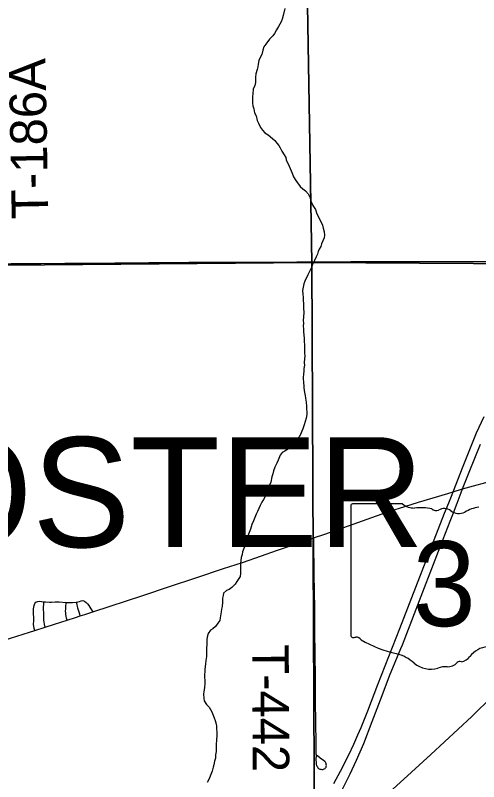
# Model space of a CAD drawing. Extents: x 0 to 34, y 0 to 22.
# Drawn here: x 6.446 to 7.165, y 18.473 to 19.661 of the extents above; entities that cross this region are included whole.
import ezdxf

# ---------------------------------------------------------------- set-up
doc = ezdxf.new("R2010")
doc.units = 0
for name, color, linetype in [('GM_X_County_Road', 7, 'Continuous'), ('GM_X_Minor_River', 7, 'Continuous'), ('GM_X_Section', 7, 'Continuous'), ('GM_X_State_Location', 7, 'Continuous'), ('GM_X_State_Route', 7, 'Continuous'), ('GM_X_State_Shield', 7, 'Continuous'), ('GM_X_Township_Road', 7, 'Continuous'), ('GM_X_Township_Road_Text', 7, 'Continuous'), ('GM_X_Township_Text', 7, 'Continuous')]:
    doc.layers.add(name, color=color, linetype=linetype)

msp = doc.modelspace()

# ---------------------------------------------------------------- linework, layer by layer
at = {"layer": 'GM_X_County_Road'}
msp.add_line((7.1398, 18.9272), (7.1984, 18.9434), dxfattribs=at)
for points in [[(6.3991, 19.2759), (6.4085, 19.2759), (6.4209, 19.2762), (6.4395, 19.2765), (6.4457, 19.2766), (6.4673, 19.2767), (6.4856, 19.2766), (6.5227, 19.277), (6.5724, 19.2772), (6.6003, 19.2775), (6.6345, 19.2778), (6.6532, 19.278), (6.6625, 19.278), (6.6904, 19.2783), (6.7153, 19.2786), (6.7463, 19.2787), (6.7711, 19.2787), (6.8478, 19.279)], [(6.8478, 19.279), (6.8518, 19.279), (6.8828, 19.2792), (6.8983, 19.2794), (6.9108, 19.2794), (6.9263, 19.2795), (6.9666, 19.2796), (6.9976, 19.2799), (7.0287, 19.2797), (7.0336, 19.2797)], [(7.0336, 19.2797), (7.0473, 19.2797), (7.072, 19.2796), (7.1029, 19.2797), (7.1215, 19.2797), (7.137, 19.2796), (7.1555, 19.2798), (7.1802, 19.28)], [(6.9143, 18.3538), (6.9217, 18.3612), (7.0032, 18.4357), (7.0604, 18.4882), (7.0903, 18.5154), (7.1541, 18.5743), (7.1635, 18.5838), (7.1761, 18.5962), (7.192, 18.6134), (7.2032, 18.626), (7.2991, 18.7318), (7.3555, 18.794), (7.3689, 18.8087)]]:
    msp.add_lwpolyline(points, dxfattribs=at)
at = {"layer": 'GM_X_Minor_River'}
for points in [[(6.8639, 19.672), (6.8614, 19.6614), (6.8596, 19.6557), (6.8581, 19.6515), (6.8544, 19.6442), (6.851, 19.6388), (6.848, 19.6335), (6.8451, 19.6296), (6.8402, 19.6246), (6.8346, 19.617), (6.8316, 19.6124), (6.8301, 19.6074), (6.8283, 19.6009), (6.8257, 19.5963), (6.8235, 19.5914), (6.8224, 19.5856), (6.8221, 19.5815), (6.821, 19.5776), (6.8192, 19.5708), (6.8185, 19.5655), (6.8186, 19.5571), (6.8175, 19.5525), (6.8149, 19.5472), (6.8143, 19.5396), (6.8136, 19.5358), (6.8137, 19.5255), (6.8145, 19.5213), (6.8157, 19.5164), (6.8169, 19.5104), (6.8193, 19.5058), (6.8213, 19.4986), (6.8229, 19.4941), (6.826, 19.4877), (6.8291, 19.4832), (6.8329, 19.4794), (6.8379, 19.4761), (6.8448, 19.4705), (6.8487, 19.4675), (6.8518, 19.4633), (6.8549, 19.4596), (6.8568, 19.4558), (6.8592, 19.4509), (6.863, 19.4453), (6.8654, 19.4411), (6.8662, 19.4373), (6.8709, 19.4275), (6.8756, 19.4169), (6.8776, 19.4113), (6.8811, 19.4056), (6.8838, 19.4018), (6.8876, 19.3962), (6.8919, 19.3925), (6.8961, 19.3895), (6.9003, 19.3846), (6.9027, 19.3801)], [(6.9027, 19.3801), (6.9039, 19.3755), (6.9051, 19.3714), (6.9074, 19.3668), (6.9113, 19.3604), (6.9129, 19.3555), (6.9148, 19.3514), (6.9203, 19.3408), (6.9223, 19.3359), (6.9235, 19.3317), (6.9251, 19.3257), (6.9255, 19.3204), (6.9252, 19.3166), (6.923, 19.3116), (6.9211, 19.3074), (6.92, 19.3032), (6.9174, 19.299), (6.9156, 19.2952), (6.9145, 19.2913), (6.9126, 19.2871), (6.9101, 19.2814), (6.9071, 19.2753), (6.9052, 19.2707), (6.903, 19.2654), (6.8997, 19.2592), (6.8949, 19.2493), (6.8934, 19.2451), (6.8923, 19.2401), (6.8916, 19.2348), (6.8917, 19.2291), (6.8922, 19.2242), (6.8922, 19.22), (6.893, 19.2143), (6.8931, 19.2075), (6.8936, 19.2007), (6.8929, 19.1938), (6.8926, 19.1885), (6.8927, 19.1843), (6.8924, 19.1797), (6.8928, 19.1756), (6.8929, 19.1706), (6.8933, 19.1661), (6.8938, 19.1604), (6.8938, 19.1551), (6.8943, 19.1509), (6.8944, 19.1384), (6.8949, 19.1331), (6.8945, 19.1292), (6.8942, 19.1228), (6.8943, 19.119), (6.8932, 19.1137), (6.8933, 19.1095), (6.8929, 19.1057), (6.8926, 19.0992), (6.8927, 19.0912), (6.8932, 19.0874), (6.8936, 19.0837), (6.8945, 19.0768), (6.8957, 19.0723), (6.8961, 19.0677), (6.8969, 19.0617), (6.8974, 19.0556), (6.8975, 19.051), (6.8983, 19.0465), (6.8979, 19.0427), (6.8973, 19.037), (6.894, 19.0267), (6.8918, 19.0206), (6.8903, 19.0168), (6.8885, 19.0118), (6.8862, 19.008), (6.8813, 19.0026), (6.8765, 18.9991), (6.872, 18.9941), (6.8678, 18.9883), (6.8641, 18.986), (6.8599, 18.9837), (6.8569, 18.9798), (6.8536, 18.9718), (6.8514, 18.9672), (6.8484, 18.9607), (6.8466, 18.9554), (6.8451, 18.9504), (6.844, 18.9462), (6.8423, 18.9375), (6.8404, 18.9329), (6.8393, 18.9287), (6.8379, 18.9241), (6.8353, 18.9192), (6.8308, 18.9107), (6.8282, 18.9069), (6.8256, 18.9016), (6.8238, 18.897), (6.8215, 18.8924), (6.8197, 18.8882), (6.8153, 18.8775), (6.8127, 18.8718), (6.8105, 18.8649), (6.8076, 18.8572), (6.8061, 18.853), (6.8046, 18.8477)], [(6.8046, 18.8477), (6.8017, 18.8386), (6.8006, 18.8347), (6.7984, 18.8298), (6.7977, 18.8256), (6.7962, 18.821), (6.7955, 18.8164), (6.7952, 18.8115), (6.7954, 18.7963), (6.7947, 18.7914), (6.7895, 18.7837), (6.7869, 18.7795), (6.782, 18.7745), (6.7775, 18.7714), (6.7733, 18.7698), (6.7688, 18.7656), (6.7681, 18.7618), (6.7674, 18.7576), (6.7671, 18.7515), (6.7668, 18.745), (6.7657, 18.7408), (6.765, 18.7366), (6.7636, 18.7275), (6.7633, 18.7233), (6.7599, 18.7191), (6.7566, 18.7137), (6.7524, 18.7103), (6.7486, 18.7083), (6.7449, 18.7033), (6.7435, 18.6976), (6.7431, 18.6938), (6.7429, 18.6854), (6.7425, 18.6809), (6.7426, 18.6725), (6.7423, 18.6672), (6.7416, 18.6611), (6.741, 18.6558), (6.7406, 18.6516), (6.7399, 18.6478), (6.74, 18.6436), (6.7396, 18.6394), (6.7398, 18.6258), (6.7392, 18.6189), (6.7385, 18.6132), (6.7378, 18.609), (6.7382, 18.603), (6.739, 18.5988), (6.7425, 18.5928), (6.7464, 18.5886), (6.7507, 18.5815), (6.7546, 18.5724), (6.7558, 18.5682), (6.757, 18.5645), (6.7578, 18.5599), (6.7582, 18.5554), (6.7587, 18.55), (6.7584, 18.544), (6.7581, 18.539), (6.7574, 18.5299), (6.7575, 18.525), (6.7572, 18.52), (6.7565, 18.5147), (6.7562, 18.5097), (6.7551, 18.5052), (6.754, 18.4995), (6.7529, 18.4956), (6.7511, 18.4895), (6.7493, 18.4846), (6.7463, 18.4769), (6.7437, 18.472)]]:
    msp.add_lwpolyline(points, dxfattribs=at)
at = {"layer": 'GM_X_Section'}
for points in [[(5.776, 20.2897), (6.8888, 20.2917), (6.9057, 19.2783), (5.7801, 19.2683), (5.7798, 19.3134)], [(7.9084, 20.2871), (7.9079, 19.2721), (6.9057, 19.2783), (6.8888, 20.2917)], [(5.7801, 19.2683), (6.9057, 19.2783), (6.9105, 18.2623), (5.7758, 18.2578), (5.7756, 18.2855)], [(6.9057, 19.2783), (7.9079, 19.2721), (7.9217, 18.2701), (6.9105, 18.2623)]]:
    msp.add_lwpolyline(points, close=True, dxfattribs=at)
at = {"layer": 'GM_X_State_Route'}
for points in [[(6.94, 18.4706), (6.9505, 18.4897), (6.9631, 18.5147), (6.971, 18.5317), (6.9774, 18.5459), (6.9823, 18.5573), (6.9928, 18.5833), (7.0085, 18.6239), (7.0253, 18.6674), (7.0423, 18.7108), (7.1019, 18.8644), (7.1119, 18.8896), (7.1182, 18.9055), (7.1234, 18.9185), (7.125, 18.9227), (7.1404, 18.9626), (7.1614, 19.0142), (7.173, 19.0396)], [(7.1398, 18.9272), (7.1501, 18.9533), (7.1675, 18.9966)], [(6.4082, 18.6865), (6.4681, 18.7052), (6.4761, 18.7078), (6.492, 18.7128), (6.5065, 18.7175), (6.5264, 18.7237), (6.5391, 18.7277), (6.5467, 18.7303), (6.5538, 18.7327), (6.5659, 18.7367), (6.6453, 18.7627), (6.6835, 18.7754), (6.7276, 18.7901), (6.769, 18.8036), (6.7985, 18.8133), (6.8279, 18.8233), (6.8513, 18.8315), (6.8894, 18.8447), (6.9089, 18.8514), (6.9099, 18.8517), (6.9245, 18.8566), (6.9625, 18.87), (7.0064, 18.8855), (7.0268, 18.8928), (7.05, 18.9002), (7.0712, 18.9069), (7.117, 18.9199), (7.125, 18.9227), (7.1398, 18.9272)], [(6.9438, 18.4431), (6.947, 18.4492), (6.9557, 18.4656), (6.9652, 18.4856), (6.9753, 18.5067), (6.9809, 18.5196), (6.9865, 18.5325), (6.9995, 18.5664), (7.0151, 18.6071), (7.0266, 18.6372), (7.0439, 18.6798), (7.0463, 18.6857), (7.0675, 18.741), (7.1024, 18.8307), (7.1204, 18.877), (7.1254, 18.8899), (7.1312, 18.9049), (7.1377, 18.9218), (7.1398, 18.9272)]]:
    msp.add_lwpolyline(points, dxfattribs=at)
at = {"layer": 'GM_X_State_Shield'}
for p, q in [((7.0463, 18.904), (6.9691, 18.904)), ((6.9665, 18.9005), (6.9665, 18.7004))]:
    msp.add_line(p, q, dxfattribs=at)
for centre, radius, start, end in [((6.9695, 18.901), 0.00305, 98.1301, 188.1301), ((7.0647, 18.9272), 0.0296, 231.6195, 271.1119), ((7.0745, 18.7916), 0.1064, 80.4867, 94.9883), ((7.0987, 18.902), 0.00855, 219.7921, 297.1024), ((7.1112, 18.8789), 0.0178, 54.4667, 119.1411), ((7.1341, 18.9106), 0.0214, 233.8562, 294.8282), ((7.1719, 18.8429), 0.0563, 97.3462, 120.7689), ((6.9695, 18.7), 0.00308, 171.9584, 258.3066), ((6.97, 18.7205), 0.0235, 267.339, 280.6039), ((6.9748, 18.6889), 0.00848, 29.7484, 93.2717), ((7.0819, 18.8687), 0.2019, 240.4129, 257.1985), ((7.1814, 18.6442), 0.0383, 94.4031, 142.5768), ((7.0217, 18.6105), 0.0632, 47.1842, 75.836), ((7.1328, 18.681), 0.0226, 282.8732, 323.2771), ((7.09, 18.6879), 0.0401, 230.7004, 286.2918), ((7.1161, 18.6729), 0.0214, 268.777, 315.5493), ((7.1354, 18.6535), 0.00601, 65.7517, 132.6484), ((7.1132, 18.6187), 0.0329, 85.6951, 111.2099)]:
    msp.add_arc(centre, radius, start, end, dxfattribs=at)
at = {"layer": 'GM_X_Township_Road'}
for points in [[(6.9127, 18.5151), (6.9123, 18.5073), (6.9124, 18.5029), (6.9126, 18.5013), (6.9128, 18.4999), (6.9132, 18.4987), (6.9138, 18.4973), (6.9144, 18.4962), (6.9153, 18.4949), (6.9163, 18.494), (6.9173, 18.4933), (6.9183, 18.4928), (6.9197, 18.4925), (6.9212, 18.4922), (6.9227, 18.4922), (6.924, 18.4925), (6.9251, 18.493), (6.9263, 18.4938), (6.9272, 18.4948), (6.9279, 18.4958), (6.9283, 18.497), (6.9284, 18.4984), (6.9283, 18.4998), (6.9281, 18.5011), (6.9277, 18.5025), (6.9269, 18.5036), (6.9259, 18.5047), (6.9239, 18.5063), (6.9188, 18.51), (6.9148, 18.5132), (6.9138, 18.5141), (6.9131, 18.5149), (6.9128, 18.5157), (6.9126, 18.5164), (6.9124, 18.5172), (6.9125, 18.5221), (6.9125, 18.5313), (6.9125, 18.542), (6.9122, 18.5568), (6.9121, 18.5678), (6.9119, 18.5765), (6.9117, 18.5867), (6.9115, 18.6023), (6.9114, 18.6125), (6.9113, 18.6226), (6.9113, 18.6295), (6.9115, 18.6457), (6.9112, 18.6601), (6.9108, 18.6856), (6.9107, 18.6918), (6.9107, 18.7184), (6.9105, 18.7317), (6.9104, 18.743), (6.9099, 18.7675), (6.9096, 18.7956), (6.9094, 18.8069), (6.9093, 18.8163), (6.9092, 18.8247), (6.9091, 18.8335), (6.909, 18.848), (6.9089, 18.8514)], [(6.4761, 18.7078), (6.4753, 18.7107), (6.4744, 18.7142), (6.4739, 18.7171), (6.4744, 18.7231), (6.4744, 18.7261), (6.4741, 18.7353), (6.4742, 18.7384), (6.4743, 18.7412), (6.4746, 18.7438), (6.4751, 18.7466), (6.476, 18.7496), (6.4779, 18.7518), (6.4806, 18.7528), (6.4836, 18.753), (6.4866, 18.7528), (6.4903, 18.7524), (6.4926, 18.7521), (6.4987, 18.7516), (6.5018, 18.7516), (6.5079, 18.752), (6.5139, 18.7519), (6.5247, 18.7513), (6.5259, 18.7512), (6.5319, 18.7513), (6.5347, 18.7513), (6.5402, 18.7516), (6.5409, 18.7517), (6.543, 18.7521), (6.5456, 18.7529), (6.5479, 18.7539), (6.5505, 18.7542), (6.5533, 18.753), (6.5557, 18.7512), (6.5578, 18.7489), (6.5597, 18.7465), (6.5614, 18.7439), (6.563, 18.7413), (6.5659, 18.7367)], [(6.492, 18.7128), (6.4911, 18.7176), (6.4905, 18.7208), (6.4901, 18.7239), (6.4899, 18.727), (6.4899, 18.736), (6.4898, 18.7391), (6.4898, 18.7421), (6.4902, 18.75), (6.4903, 18.7524)], [(6.5264, 18.7237), (6.5255, 18.7268), (6.5247, 18.7298), (6.5242, 18.7324), (6.524, 18.7351), (6.5239, 18.7379), (6.524, 18.741), (6.5242, 18.744), (6.5247, 18.7513)], [(6.5467, 18.7303), (6.5459, 18.7329), (6.5439, 18.7392), (6.5431, 18.7424), (6.5424, 18.7453), (6.5419, 18.7474), (6.5412, 18.7501), (6.5409, 18.7517)]]:
    msp.add_lwpolyline(points, dxfattribs=at)

# ---------------------------------------------------------------- texts
at = {"layer": 'GM_X_State_Location'}
for s in ['s', 'r']:
    msp.add_text(s, height=0.000189, dxfattribs=at).set_placement((7.0953, 18.7872))
msp.add_text('3', height=0.000189, rotation=0, dxfattribs=at).set_placement((7.0668, 18.7734))
at = {"layer": 'GM_X_State_Shield'}
msp.add_text('3', height=0.1318, dxfattribs=at).set_placement((7.0622, 18.7145))
at = {"layer": 'GM_X_Township_Road_Text'}
for s, rotation, p in [('T-186A', 91.0706, (6.4972, 19.3462)), ('T-442', 270.2824, (6.8132, 18.6864))]:
    msp.add_text(s, height=0.05682, rotation=rotation, dxfattribs=at).set_placement(p)
at = {"layer": 'GM_X_Township_Text'}
msp.add_text('WOOSTER', height=0.17045, rotation=0, dxfattribs=at).set_placement((5.9025, 18.837))

doc.saveas('drawing.dxf')
